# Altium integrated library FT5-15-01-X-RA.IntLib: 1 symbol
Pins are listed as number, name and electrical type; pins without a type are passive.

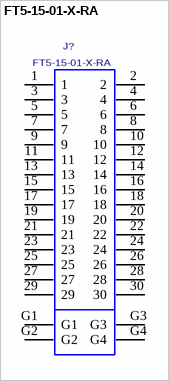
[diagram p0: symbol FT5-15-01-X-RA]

## FT5-15-01-X-RA
designator J?
0.5mm PITCH, RA TERMINAL STRIP ASSEMBLY.; MANUFACTURER: SAMTEC
footprint FT5-15-01-X-RA
pins: 1, 2, 3, 4, 5, 6, 7, 8, 9, 10, 11, 12, 13, 14, 15, 16, 17, 18, 19, 20, 21, 22, 23, 24, 25, 26, 27, 28, 29, 30, G1, G2, G3, G4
